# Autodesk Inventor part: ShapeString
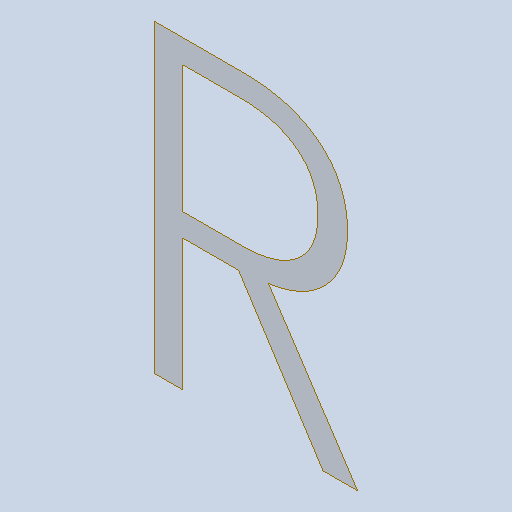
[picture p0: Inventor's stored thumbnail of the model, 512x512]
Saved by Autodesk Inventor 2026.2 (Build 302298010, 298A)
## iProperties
Created: 2026-10
Part Number: ShapeString
Material: Générique
Document SubType Name: Modeling
Designer: mel
Density: 1 g/cm^3
Appearance: Par défaut
Author: mel
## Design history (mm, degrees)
feature "Composite1"
body "Srf1"
